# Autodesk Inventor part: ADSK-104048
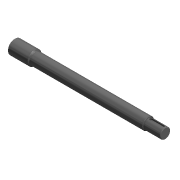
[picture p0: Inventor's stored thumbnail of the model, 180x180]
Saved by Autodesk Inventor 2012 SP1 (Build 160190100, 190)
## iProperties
Shininess: 0.0
Created: 2000-11
Part Number: ADSK-104048
Description: AISI 1040 DIA. 2-1/4" x 22-1/2" LONG
Document SubType Name: Modeling
Stock Number: ADSK-104048
Density: 1 g/cm^3
Material: Default
Density: 0.0
Volumn: 0.0
Area: 0.0
PropertySet Name: Model Information
Control State: 0
Master: False
Checked Out: False
Author: gao
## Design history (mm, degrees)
node "Revolution1" dims "d8" = 360 deg
  sketch "Sketch1"
    geometry: L1 (-27.875, 14.644)-(48.325, 14.644); L2 (537.275, 7.504)-(537.275, -11.55); L3 (537.275, -11.55)-(-27.875, -11.55); L4 (-27.875, -11.55)-(-27.875, 14.644); L5 (48.325, 14.644)-(48.325, 10.675); L6 (48.325, 10.675)-(397.575, 10.675); L7 (397.575, 10.675)-(397.575, 10.675); L8 (397.575, 10.675)-(473.775, 10.675); L9 (473.775, 10.675)-(473.775, 7.504); L10 (473.775, 7.504)-(537.275, 7.504)
    constraints: 20 end point, 5 parallel, 4 perpendicular, 1 horizontal
    dimensions: "d0" = 26.19375 distance of L3.end L1.start; "d1" = 565.15 distance of L2.end L3.end; "d2" = 76.2 distance of L1.end L1.start; "d3" = 63.5 distance of L9.end L2.start; "d4" = 76.2 distance of L7.end L8.end; "d5" = 22.225 distance between parallel lines of L3 L6; "d6" = 22.225 distance between parallel lines of L3 L8; "d7" = 19.05365 distance between parallel lines of L3 L10
node "Chamfer1" dims "d9" = 1.5875, "d10" = 1.5875, "d22" = 45 deg
node "Chamfer2" dims "d11" = 1.5875, "d12" = 1.5875, "d23" = 45 deg
node "Chamfer3" dims "d14" = 1.5875, "d15" = 1.5875, "d24" = 45 deg
workaxis "Work Axis1"
workplane "Work Plane1"
node "Extrusion1" dims "d19" = 4.7625, "d20" = 0
  sketch "Sketch2"
    geometry: L1 (646.43, 0)-(-144.78, 0) reference; L2 (-22.225, -4.763)-(22.225, -4.763); L3 (-22.225, 4.763)-(22.225, 4.763); L4 (-31.75, -17.466)-(-31.75, 17.466) reference; A1 r 4.763 centre (-22.225, 0) between (-22.225, 4.763) and (-22.225, -4.763); A2 r 4.763 centre (22.225, 0) between (22.225, -4.763) and (22.225, 4.763)
    constraints: 4 end point, 4 point on circle, 3 tangent, 2 centre point, 2 point on line, 1 equal radius, 1 parallel
    dimensions: "d16" = 9.525 diameter of A1; "d17" = 9.525 distance from line of L4 A1.centre; "d18" = 44.45 distance of A2.centre A1.centre
node "Fillet2" dims "d21" = 3.175
body "Solid1"
